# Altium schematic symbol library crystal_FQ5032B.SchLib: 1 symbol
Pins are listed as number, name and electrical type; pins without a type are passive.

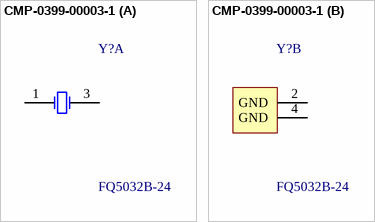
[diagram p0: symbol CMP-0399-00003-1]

## CMP-0399-00003-1
designator Y?, comment FQ5032B-24
Crystal Oscillator, SMD, 24MHz, Stab=30ppm 20.0pF; Manufacturer: FOX Electronics; Frequency Tolerance: 30 ppm
footprint FOX-FQ5032B_V (SMT Crystal, 4-Leads, Body 5.2x3.4mm)
part A pins: 1 X1, 3 X2
part B pins: 2 GND, 4 GND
